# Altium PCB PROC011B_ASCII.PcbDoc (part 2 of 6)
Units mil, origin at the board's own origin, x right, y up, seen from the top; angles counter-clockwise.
Board outline 3304 x 2569 mil, 6 copper layers (TOP, L2-GND1, L3-GND/SIG, L4-GND/SIG, L5-GND2, BOTTOM), stack 55.77 mil thick; 376 components, 289 nets, 1284 pads, 1755 vias.
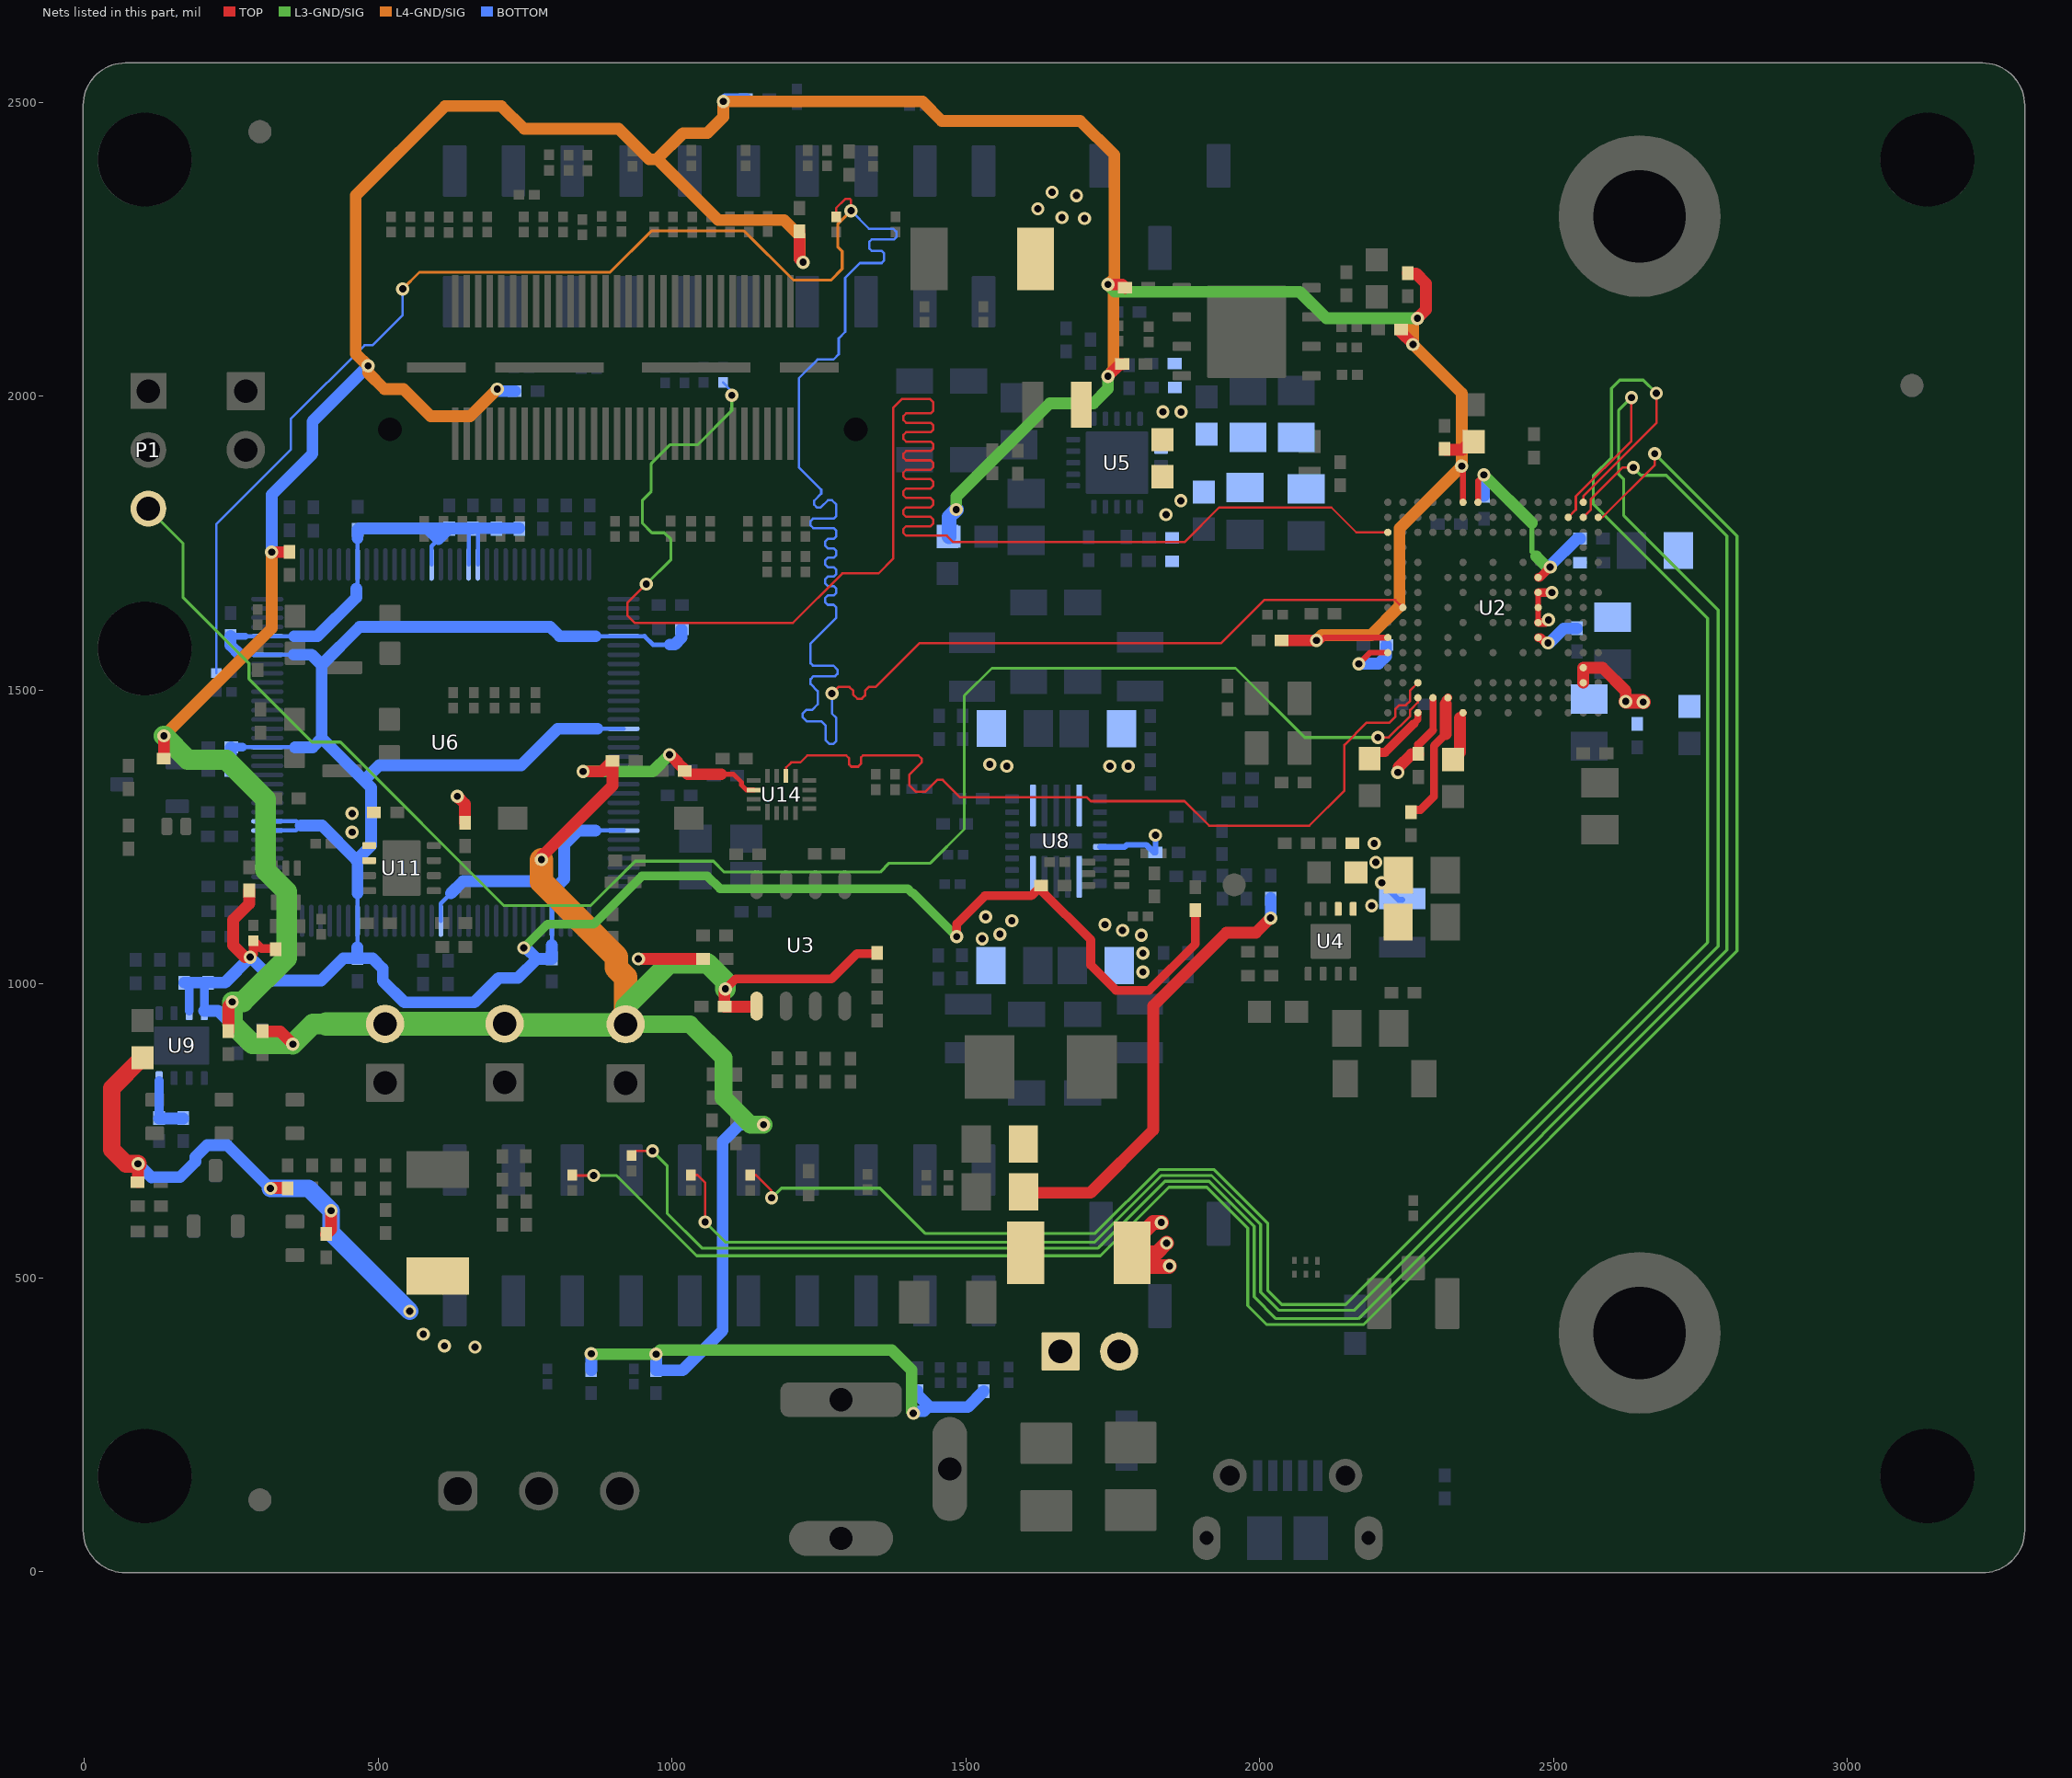
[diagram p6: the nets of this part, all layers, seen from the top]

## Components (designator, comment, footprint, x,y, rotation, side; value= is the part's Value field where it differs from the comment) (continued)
R204 "CRCW04023R83FKED" 0402L 1493.45,1029.3 r270 bottom
R205 "CRCW04023R83FKED" 0402L 1836.65,1032.8 r270 bottom
R206 "CRCW040210K0FKED" 0402L 918.61,1379.34 r180 top locked
R208 "CRCW040210K0FKED" 0402L 1105.82,1383.62 r180 top locked
R210 "CRCW02010000Z0ED" 0201 2026.48,1628.29 r0 top
R211 "CRCW02010000Z0ED" 0201 1421.16,1331.73 r0 bottom
S2 "CHS-01TB" SW_CHS-01TB 878.93,1281.85 r90 top locked
SW1 "KMR243GLFG" SW_KMR243GLFG 439.4,1594.12 r180 top
SW2 "KMR243GLFG" SW_KMR243GLFG 438.45,1418.5 r180 top
U1 "MX25V1635FZNQ" WSON-8L_6x5MM_EP 1977.88,2109.68 r0 top
U2 "X1642BIGABL" ABL0161B 2397.3,1640.4 r180 top
U3 "TCAN1042HGVDQ1" D0008A_L 1219.06,1065.48 r270 top
U4 "TPS7A8101QDRBRQ1" DRB0008A 2120.93,1072.47 r270 top
U5 "TPS7A8801RTJR" RTJ0020D 1757.37,1886.82 r0 bottom
U6 "TM4C1294NCPDTT3" PDT0128A 614.54,1410.54 r0 bottom
U7 "LM4040C25QDBZR" DBZ0003A_N 110.83,1339.59 r180 bottom
U8 "LP87524BRNFRQ1" RNF0026C 1653.75,1243 r0 bottom
U9 "TPS79601DRBR" DRB0008B 165.58,894.88 r270 bottom
U10 "TPD4E004DRYR" DRY0006A 2078.75,518 r270 top
U11 "TPS79601DRBR" DRB0008B 539.65,1197 r0 top
U12 "TMP112AIDRLR" DRL0006A 1736.25,1187.4 r0 top
U13 "TMP112AIDRLR" DRL0006A 342.75,1167.9 r270 top
U14 "TS3A5018RSVR" RSV0016A 1186.27,1322.21 r90 top locked
Y1 "CX3225SA40000D0PTWCC" KYOCERA_CX3225SA 2031.47,1443.64 r0 top
Y2 "NX3225SA-16.000M-STD-CRS-2" NDK_NX3225SA 1083.39,1215.58 r270 bottom
ZZ1 "This Assembly Note is for PCB labels only" AssemblyNoteLabel -70,3780 r0 top
ZZ2 "These assemblies are ESD sensitive, ESD precautions shall be observed." AssemblyNote -70,3690 r0 top
ZZ3 "These assemblies must be clean and free from flux and all contaminants. Use of no clean flux is not acceptable." AssemblyNote -70,3590 r0 top
ZZ4 "These assemblies must comply with workmanship standards IPC-A-610 Class 2, unless otherwise specified." AssemblyNote -70,3500 r0 top
ZZ5 "Micro USB cable, Brackets, Screws, Nuts, Jumpers and Bump on need to be place in a plastic bag" AssemblyNote -76,3400 r90 top

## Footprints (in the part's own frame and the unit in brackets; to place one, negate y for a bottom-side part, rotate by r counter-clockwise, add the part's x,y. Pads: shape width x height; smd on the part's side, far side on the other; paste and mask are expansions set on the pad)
0201 [mm] "Data from Kemet datasheet CC101_COM dated 7/28/11"
  rect 0.46x0.42 smd: 1(-0.33,0) 2(0.33,0)
0201_033 [mm] "SMD, 2-Leads, Height 0.33mm"
  rect 0.46x0.42 smd mask+0: 1(-0.33,0) 2(0.33,0)
0201_Silk [mm] "Data from Kemet datasheet CC101_COM dated 7/28/11"
  rect 0.46x0.42 smd mask+0: 1(-0.33,0) 2(0.33,0)
  silkscreen extent -0.75,-0.4 0.75,0.4
0402_065L [mm] "0402"
  rect 0.6x0.5 smd: 1(-0.5,0) 2(0.5,0)
0402L [mm] "0402 from SM-752 data"
  rect 0.6x0.5 smd: 1(-0.5,0) 2(0.5,0)
0603 [mm] "0603 from SM-752 data"
  rect 1x0.95 smd: 1(-0.8,0) 2(0.8,0)
  silkscreen extent -1.52,-0.69 1.52,0.69
0805_HV [mil] "0805 with 30mil clearance between pads"
  rect 50x63 smd: 1(-40,0) 2(40,0)
  silkscreen extent -74,-40 74,40
1206 [mm] "1206 from SM-752 data"
  rect 1.3x1.85 smd: 1(-1.45,0) 2(1.45,0)
  silkscreen extent -2.4,-1.21 2.4,1.21
1206_180 [mm] "1206_180"
  rect 1.1x1.6 smd: 1(-1.7,0) 2(1.7,0)
  silkscreen extent -0.9,-1 0.9,1
2010 [mm] "Chip Capacitor, Body 5.08x2.54mm, IPC Medium Density"
  rect 1.6x2.7 smd: 1(-2.3,0) 2(2.3,0)
  silkscreen extent -3.29,-1.65 3.42,1.65
3528-21 [mm] "Medium Density IPC, based on Kemet datasheet 2016-10-20"
  rrect6% 1.8x2.23 smd: 1(-1.46,0) 2(1.46,0)
  silkscreen extent -2.29,-1.5 0.76,1.5
ABL0161B [mm] "BGA, 161-Balls, Body 10.4x10.4mm, Pitch 0.65mm"
  round 0.32 smd: A1(-4.55,4.55) A2(-3.9,4.55) A3(-3.25,4.55) A5(-1.95,4.55) A7(-0.65,4.55) A9(0.65,4.55) A10(1.3,4.55) A13(3.25,4.55) A14(3.9,4.55) A15(4.55,4.55) B1(-4.55,3.9) B2(-3.9,3.9) B3(-3.25,3.9) B4(-2.6,3.9) B5(-1.95,3.9) B6(-1.3,3.9) B7(-0.65,3.9) B8(0,3.9) B9(0.65,3.9) B10(1.3,3.9) B11(1.95,3.9) B12(2.6,3.9) B13(3.25,3.9) B14(3.9,3.9) B15(4.55,3.9) C1(-4.55,3.25) C2(-3.9,3.25) C3(-3.25,3.25) C4(-2.6,3.25) C5(-1.95,3.25) C6(-1.3,3.25) C7(-0.65,3.25) C8(0,3.25) C9(0.65,3.25) C13(3.25,3.25) C14(3.9,3.25) C15(4.55,3.25) D2(-3.9,2.6) D13(3.25,2.6) D14(3.9,2.6) D15(4.55,2.6) E1(-4.55,1.95) E2(-3.9,1.95) E3(-3.25,1.95) E5(-1.95,1.95) E6(-1.3,1.95) E8(0,1.95) E10(1.3,1.95) E11(1.95,1.95) E13(3.25,1.95) E14(3.9,1.95) E15(4.55,1.95) F2(-3.9,1.3) F3(-3.25,1.3) F5(-1.95,1.3) F9(0.65,1.3) F11(1.95,1.3) F13(3.25,1.3) F14(3.9,1.3) F15(4.55,1.3) G1(-4.55,0.65) G2(-3.9,0.65) G3(-3.25,0.65) G5(-1.95,0.65) G6(-1.3,0.65) G7(-0.65,0.65) G8(0,0.65) G10(1.3,0.65) G13(3.25,0.65) G14(3.9,0.65) G15(4.55,0.65) H2(-3.9,0) H3(-3.25,0) H5(-1.95,0) H7(-0.65,0) H9(0.65,0) H11(1.95,0) H13(3.25,0) H14(3.9,0) H15(4.55,0) J1(-4.55,-0.65) J2(-3.9,-0.65) J3(-3.25,-0.65) J5(-1.95,-0.65) J6(-1.3,-0.65) J7(-0.65,-0.65) J8(0,-0.65) J10(1.3,-0.65) J13(3.25,-0.65) J14(3.9,-0.65) J15(4.55,-0.65) K2(-3.9,-1.3) K3(-3.25,-1.3) K5(-1.95,-1.3) K7(-0.65,-1.3) K8(0,-1.3) K9(0.65,-1.3) K10(1.3,-1.3) K11(1.95,-1.3) K13(3.25,-1.3) K14(3.9,-1.3) K15(4.55,-1.3) L1(-4.55,-1.95) L2(-3.9,-1.95) L3(-3.25,-1.95) L5(-1.95,-1.95) L6(-1.3,-1.95) L8(0,-1.95) L10(1.3,-1.95) L13(3.25,-1.95) L14(3.9,-1.95) L15(4.55,-1.95) M2(-3.9,-2.6) M3(-3.25,-2.6) M14(3.9,-2.6) M15(4.55,-2.6) N1(-4.55,-3.25) N2(-3.9,-3.25) N3(-3.25,-3.25) N4(-2.6,-3.25) N5(-1.95,-3.25) N6(-1.3,-3.25) N7(-0.65,-3.25) N8(0,-3.25) N9(0.65,-3.25) N10(1.3,-3.25) N11(1.95,-3.25) N12(2.6,-3.25) N13(3.25,-3.25) N14(3.9,-3.25) N15(4.55,-3.25) P1(-4.55,-3.9) P2(-3.9,-3.9) P3(-3.25,-3.9) P4(-2.6,-3.9) P5(-1.95,-3.9) P6(-1.3,-3.9) P7(-0.65,-3.9) P8(0,-3.9) P9(0.65,-3.9) P10(1.3,-3.9) P11(1.95,-3.9) P12(2.6,-3.9) P13(3.25,-3.9) P14(3.9,-3.9) P15(4.55,-3.9) R1(-4.55,-4.55) R2(-3.9,-4.55) R3(-3.25,-4.55) R4(-2.6,-4.55) R5(-1.95,-4.55) R6(-1.3,-4.55) R7(-0.65,-4.55) R8(0,-4.55) R9(0.65,-4.55) R10(1.3,-4.55) R11(1.95,-4.55) R12(2.6,-4.55) R13(3.25,-4.55) R14(3.9,-4.55) R15(4.55,-4.55)
  silkscreen extent -5.3,-5.3 5.3,5.3
AssemblyNote [mil] "Assembly Note"
AssemblyNoteLabel [mil] "Assembly Note for PCB Labels"
CE_Mark_5mm [mil] "Minimum text height for CE Mark"
CONN_105017-0001 [mm] "Molex Micro USB-B"
  rect 0.4x1.35 smd: 1(-1.3,1.35) 2(-0.65,1.35) 3(0,1.35) 4(0.65,1.35) 5(1.3,1.35)
  oval 1.2x1.9 hole 0.6 slot 1.3 at 90 deg: 6(-3.5,-1.35) 9(3.5,-1.35)
  rect 1.5x1.9 smd: 7(-1,-1.35) 8(1,-1.35)
  round 1.45 hole 0.85: 10(2.5,1.35) 11(-2.5,1.35)
  TOP region: 3.5,-2.3 2.3,-2.3 2.3,-0.4 3.5,-0.4
  TOP region: -3.5,-0.4 -2.3,-0.4 -2.3,-2.3 -3.5,-2.3
  silkscreen extent -4.1,-0.2 4.1,1.4
CUI_PJ-002AH [mm] "DC POWER JACK, R/A, TH"
  rrect50% 1.5x5.25 hole 1 square: 1(-3,0)
  oval 1.5x4.5 hole 1 square: 2(3,0)
  oval 4.5x1.5 hole 1 square: 3(0,4.7)
  silkscreen extent -4.1,-4.5 10.7,4.5
D0008A_L [mm] "SOIC, 8-Leads, Body 4.9x3.9mm, Pitch 1.27mm, IPC High Density"
  oval 1.25x0.55 smd: 1(-2.625,1.905) 2(-2.625,0.635) 3(-2.625,-0.635) 4(-2.625,-1.905) 5(2.625,-1.905) 6(2.625,-0.635) 7(2.625,0.635) 8(2.625,1.905)
  silkscreen extent -3.1,-2.5 0.9,2.5
DBZ0003A_N [mm] "SOT23, 3-Leads, Body 2.9x1.3mm, Pitch 0.95mm, Lead Span 2.4mm, IPC Medium Density"
  rrect17% 1x0.6 smd: 1(-1.2,0.95) 2(-1.2,-0.95) 3(1.2,0)
  silkscreen extent 0.2,-1.5 0.7,1.5
DFE252012P [mm] "TOKO, Pad sizes increased as per request"
  rect 0.9x2 smd: 1(-1.05,0) 2(1.05,0)
  silkscreen extent -0.3,-1.2 0.3,1.2
DRB0008A [mm] "SON, 8-Leads, Body 3x3mm, Pitch 0.65mm, Thermal Pad 1.75x1.5mm, TI Recommended"
  rrect33% 0.6x0.3 smd: 1(-1.4,0.975) 2(-1.4,0.325) 3(-1.4,-0.325) 4(-1.4,-0.975) 5(1.4,-0.975) 6(1.4,-0.325) 7(1.4,0.325) 8(1.4,0.975)
  rrect7% 1.5x1.75 smd paste-0.75: 9(0,0)
  silkscreen extent -1.73,-1.73 1.73,1.73
DRB0008B [mm] "SON, 8-Leads, Body 3x3mm, Pitch 0.65mm, Thermal Pad 2.4x1.65mm, TI Recommended"
  rrect33% 0.6x0.3 smd: 1(-1.4,0.975) 2(-1.4,0.325) 3(-1.4,-0.325) 4(-1.4,-0.975) 5(1.4,-0.975) 6(1.4,-0.325) 7(1.4,0.325) 8(1.4,0.975)
  rrect6% 1.65x2.4 smd paste-1.2: 9(0,0)
  silkscreen extent -1.73,-1.73 1.73,1.73
DRL0006A [mm] "SOTFL, 6-Flat Leads, Body 1.2x1.6x0.6mm, Pitch 0.5mm, TI recommended"
  rrect33% 0.67x0.3 smd: 1(-0.74,0.5) 2(-0.74,0) 3(-0.74,-0.5) 4(0.74,-0.5) 5(0.74,0) 6(0.74,0.5)
  silkscreen extent -0.9,-0.95 0.5,0.95
DRY0006A [mm] "PSON, 6-Leads, Body 1x1.45mm, Pitch 0.5mm, TI Recommended"
  rect 0.35x0.2 smd: 1(-0.275,0.5)
  rect 0.3x0.2 smd: 2(-0.3,0) 3(-0.3,-0.5) 4(0.3,-0.5) 5(0.3,0) 6(0.3,0.5)
  silkscreen extent -0.5,-0.85 0.2,0.85
ESD_Overlay_Small [mil]
  silkscreen extent -62,-48 64,61
FCC_disclaimer [mil]
FIDUCIAL10-20 [mm]
  round 1 smd mask+0: 1(0,0)
  TOP keep-out circle w1.178: c0,0 r0.5
Fiducial10-20 [mm]
  round 1 smd mask+0: 1(0,0)
  TOP keep-out circle w1.178: c0,0 r0.5
IEC_HotSurface_Small [mil]
  silkscreen extent -107,-93 107,92
JOHNSON_128-0711-201 [mm] "UMC Straight Jack Receptacle, 50 Ohm, SMT"
  rrect10% 1x1.05 smd: 1(0,1.525)
  rrect10% 1.05x2.2 smd: 2(-1.475,0) 3(1.475,0)
  silkscreen extent -0.6,-1.3 0.6,-1.3
KYOCERA_CX3225SA [mm] "SMD, 4-Leads, Body 3.2x2.5mm"
  rrect10% 1.05x1.45 smd: 1(-0.925,1.075) 2(-0.925,-1.075) 3(0.925,-1.075) 4(0.925,1.075)
  silkscreen extent -1.83,1.05 -1.71,1.18
Label_650x200 [mil] "Thermal Transfer Label"
  round 1 on Mech13: 0(0,0)
  silkscreen extent -325,-100 325,100
NDK_NX3225SA [mm] "NDK"
  rect 1.2x1.4 smd: 1(-0.8,1.1) 2(-0.8,-1.1) 3(0.8,-1.1) 4(0.8,1.1)
ON-SHORE_OSTTE030161 [mm] "Terminal Block, 3.5mm, 3x1, TH"
  rrect50% 1.7x1.7 hole 1.2: 1(-3.5,0)
  round 1.7 hole 1.2: 2(0,0) 3(3.5,0)
  silkscreen extent -5.25,-3.6 5.25,4.05
PDT0128A [mm] "Thin QFP, 128-Leads, Body 14x14mm, Pitch 0.4mm"
  oval 1.4x0.2 smd: 1(-7.7,6.2) 2(-7.7,5.8) 3(-7.7,5.4) 4(-7.7,5) 5(-7.7,4.6) 6(-7.7,4.2) 7(-7.7,3.8) 8(-7.7,3.4) 9(-7.7,3) 10(-7.7,2.6) 11(-7.7,2.2) 12(-7.7,1.8) 13(-7.7,1.4) 14(-7.7,1) 15(-7.7,0.6) 16(-7.7,0.2) 17(-7.7,-0.2) 18(-7.7,-0.6) 19(-7.7,-1) 20(-7.7,-1.4) 21(-7.7,-1.8) 22(-7.7,-2.2) 23(-7.7,-2.6) 24(-7.7,-3) 25(-7.7,-3.4) 26(-7.7,-3.8) 27(-7.7,-4.2) 28(-7.7,-4.6) 29(-7.7,-5) 30(-7.7,-5.4) 31(-7.7,-5.8) 32(-7.7,-6.2) 65(7.7,-6.2) 66(7.7,-5.8) 67(7.7,-5.4) 68(7.7,-5) 69(7.7,-4.6) 70(7.7,-4.2) 71(7.7,-3.8) 72(7.7,-3.4) 73(7.7,-3) 74(7.7,-2.6) 75(7.7,-2.2) 76(7.7,-1.8) 77(7.7,-1.4) 78(7.7,-1) 79(7.7,-0.6) 80(7.7,-0.2) 81(7.7,0.2) 82(7.7,0.6) 83(7.7,1) 84(7.7,1.4) 85(7.7,1.8) 86(7.7,2.2) 87(7.7,2.6) 88(7.7,3) 89(7.7,3.4) 90(7.7,3.8) 91(7.7,4.2) 92(7.7,4.6) 93(7.7,5) 94(7.7,5.4) 95(7.7,5.8) 96(7.7,6.2)
  oval 0.2x1.4 smd: 33(-6.2,-7.7) 34(-5.8,-7.7) 35(-5.4,-7.7) 36(-5,-7.7) 37(-4.6,-7.7) 38(-4.2,-7.7) 39(-3.8,-7.7) 40(-3.4,-7.7) 41(-3,-7.7) 42(-2.6,-7.7) 43(-2.2,-7.7) 44(-1.8,-7.7) 45(-1.4,-7.7) 46(-1,-7.7) 47(-0.6,-7.7) 48(-0.2,-7.7) 49(0.2,-7.7) 50(0.6,-7.7) 51(1,-7.7) 52(1.4,-7.7) 53(1.8,-7.7) 54(2.2,-7.7) 55(2.6,-7.7) 56(3,-7.7) 57(3.4,-7.7) 58(3.8,-7.7) 59(4.2,-7.7) 60(4.6,-7.7) 61(5,-7.7) 62(5.4,-7.7) 63(5.8,-7.7) 64(6.2,-7.7) 97(6.2,7.7) 98(5.8,7.7) 99(5.4,7.7) 100(5,7.7) 101(4.6,7.7) 102(4.2,7.7) 103(3.8,7.7) 104(3.4,7.7) 105(3,7.7) 106(2.6,7.7) 107(2.2,7.7) 108(1.8,7.7) 109(1.4,7.7) 110(1,7.7) 111(0.6,7.7) 112(0.2,7.7) 113(-0.2,7.7) 114(-0.6,7.7) 115(-1,7.7) 116(-1.4,7.7) 117(-1.8,7.7) 118(-2.2,7.7) 119(-2.6,7.7) 120(-3,7.7) 121(-3.4,7.7) 122(-3.8,7.7) 123(-4.2,7.7) 124(-4.6,7.7) 125(-5,7.7) 126(-5.4,7.7) 127(-5.8,7.7) 128(-6.2,7.7)
  silkscreen extent -7.7,-6.3 6.3,6.99
RNF0026C [mm] "QFN, 26-Leads, Body 4x4.5mm, Pitch 0.5mm"
  rrect25% 0.6x0.4 smd paste-0.3: 1(-1.9,1.825) 8(-1.9,-1.825) 14(1.9,-1.825) 21(1.9,1.825)
  rrect40% 0.6x0.25 smd paste+0: 2(-1.9,1.25) 3(-1.9,0.75) 4(-1.9,0.25) 5(-1.9,-0.25) 6(-1.9,-0.75) 7(-1.9,-1.25) 15(1.9,-1.25) 16(1.9,-0.75) 17(1.9,-0.25) 18(1.9,0.25) 19(1.9,0.75) 20(1.9,1.25)
  rrect40% 0.25x1.82 smd paste-1: 9(-1,-1.54) 10(-0.5,-1.54) 11(0,-1.54) 12(0.5,-1.54) 13(1,-1.54) 22(1,1.54) 23(0.5,1.54) 24(0,1.54) 25(-0.5,1.54) 26(-1,1.54)
  rrect15% 2.24x0.66 smd paste-1: 27(0,0)
  rrect50% 0.6x0.3 on Bottom Paste: ""(-1.9,-1.775) ""(-1.9,1.775) ""(1.9,-1.775) ""(1.9,1.775)
  rrect50% 0.3x0.825 on Bottom Paste: ""(-1.575,-2.037) ""(-1.575,2.037) ""(1.575,-2.037) ""(1.575,2.037)
  rrect50% 0.25x0.81 on Bottom Paste: ""(-1,-2.045) ""(-1,-1.035) ""(-1,1.035) ""(-1,2.045) ""(-0.5,-2.045) ""(-0.5,-1.035) ""(-0.5,1.035) ""(-0.5,2.045) ""(0,-2.045) ""(0,-1.035) ""(0,1.035) ""(0,2.045) ""(0.5,-2.045) ""(0.5,-1.035) ""(0.5,1.035) ""(0.5,2.045) ""(1,-2.045) ""(1,-1.035) ""(1,1.035) ""(1,2.045)
  rrect50% 0.98x0.66 on Bottom Paste: ""(-0.59,0) ""(0.59,0)
  silkscreen extent -2.45,-2.7 2.45,2.7
RSV0016A [mm] "QFN, 16-Leads, Body 1.8x2.6mm, Pitch 0.4mm, TI Recommended"
  rect 0.7x0.2 smd: 1(-0.75,0.6)
  rect 0.6x0.2 smd: 2(-0.8,0.2) 3(-0.8,-0.2) 4(-0.8,-0.6) 9(0.8,-0.6) 10(0.8,-0.2) 11(0.8,0.2) 12(0.8,0.6)
  rect 0.2x0.6 smd: 5(-0.6,-1.2) 6(-0.2,-1.2) 7(0.2,-1.2) 8(0.6,-1.2) 13(0.6,1.2) 14(0.2,1.2) 15(-0.2,1.2) 16(-0.6,1.2)
  silkscreen extent -1.08,-1.33 1.08,1.45
RTJ0020D [mm] "QFN, 20-Leads, Body 4x4mm, Pitch 0.5mm, Thermal Pad 2.7x2.7mm, TI Recommended"
  rrect42% 0.6x0.24 smd: 1(-1.9,1) 2(-1.9,0.5) 3(-1.9,0) 4(-1.9,-0.5) 5(-1.9,-1) 11(1.9,-1) 12(1.9,-0.5) 13(1.9,0) 14(1.9,0.5) 15(1.9,1)
  rrect42% 0.24x0.6 smd: 6(-1,-1.9) 7(-0.5,-1.9) 8(0,-1.9) 9(0.5,-1.9) 10(1,-1.9) 16(1,1.9) 17(0.5,1.9) 18(0,1.9) 19(-0.5,1.9) 20(-1,1.9)
  rrect50% 1.19x1.19 on Bottom Paste: 21(-0.695,-0.695) 21(-0.695,0.695) 21(0.695,-0.695) 21(0.695,0.695)
  rrect4% 2.7x2.7 smd paste-1.4: 21(0,0)
  silkscreen extent -2.22,-2.22 2.23,2.22
SAMTEC_QSH-030-01-X-D-A [mm] "Receptacle, 0.5 mm, 30x2, TH"
  rect 2.27x0.279 smd: 1(-2.865,7.25) 2(2.865,7.25) 3(-2.865,6.75) 4(2.865,6.75) 5(-2.865,6.25) 6(2.865,6.25) 7(-2.865,5.75) 8(2.865,5.75) 9(-2.865,5.25) 10(2.865,5.25) 11(-2.865,4.75) 12(2.865,4.75) 13(-2.865,4.25) 14(2.865,4.25) 15(-2.865,3.75) 16(2.865,3.75) 17(-2.865,3.25) 18(2.865,3.25) 19(-2.865,2.75) 20(2.865,2.75) 21(-2.865,2.25) 22(2.865,2.25) 23(-2.865,1.75) 24(2.865,1.75) 25(-2.865,1.25) 26(2.865,1.25) 27(-2.865,0.75) 28(2.865,0.75) 29(-2.865,0.25) 30(2.865,0.25) 31(-2.865,-0.25) 32(2.865,-0.25) 33(-2.865,-0.75) 34(2.865,-0.75) 35(-2.865,-1.25) 36(2.865,-1.25) 37(-2.865,-1.75) 38(2.865,-1.75) 39(-2.865,-2.25) 40(2.865,-2.25) 41(-2.865,-2.75) 42(2.865,-2.75) 43(-2.865,-3.25) 44(2.865,-3.25) 45(-2.865,-3.75) 46(2.865,-3.75) 47(-2.865,-4.25) 48(2.865,-4.25) 49(-2.865,-4.75) 50(2.865,-4.75) 51(-2.865,-5.25) 52(2.865,-5.25) 53(-2.865,-5.75) 54(2.865,-5.75) 55(-2.865,-6.25) 56(2.865,-6.25) 57(-2.865,-6.75) 58(2.865,-6.75) 59(-2.865,-7.25) 60(2.865,-7.25)
  round 0 hole 1.02 unplated mask+0: MH1(2.67,10.065) MH2(2.67,-10.065)
  rect 0.43x2.54 smd: MP1(0,8.065) MP4(0,-8.065)
  rect 0.43x4.7 smd: MP2(0,3.175) MP3(0,-3.175)
  silkscreen extent -3.9,-10.66 3.62,10.66
SAMTEC_SSM-103-X-SV [mm] "Receptacle, 2.54mm, 3x1, SMT"
  rrect10% 1.02x1.905 smd: 1(-2.54,-1.777) 2(0,1.777) 3(2.54,-1.777)
  silkscreen extent -3.81,-2.27 3.81,1.28
SAMTEC_SSM-110-X-DV [mm] "Receptacle, 2.54mm, 10x2, SMT"
  rrect10% 1.02x2.22 smd: 1(-11.43,2.825) 2(-11.43,-2.825) 3(-8.89,2.825) 4(-8.89,-2.825) 5(-6.35,2.825) 6(-6.35,-2.825) 7(-3.81,2.825) 8(-3.81,-2.825) 9(-1.27,2.825) 10(-1.27,-2.825) 11(1.27,2.825) 12(1.27,-2.825) 13(3.81,2.825) 14(3.81,-2.825) 15(6.35,2.825) 16(6.35,-2.825) 17(8.89,2.825) 18(8.89,-2.825) 19(11.43,2.825) 20(11.43,-2.825)
  silkscreen extent -13.02,-2.54 12.7,2.54
SAMTEC_TSW-103-07-T-S [mm] "Header, 2.54 mm, 3x1, TH"
  rect 1.55x1.55 hole 1.02: 1(-2.54,0)
  round 1.55 hole 1.02: 2(0,0) 3(2.54,0)
  silkscreen extent -3.81,-1.75 3.81,1.27
SMB [mil] "Molded Diode, 2-Leads, Body 5.4x3.6mm, IPC Medium Density, based on OnSemi component dimensions"
  rect 85x107.99 smd: 1(-87.01,0) 2(87.01,0)
  silkscreen extent -155,-82 125,82
SOD-882 [mm] "Skyworks"
  rrect42% 0.475x0.75 smd: 1(-0.412,0) 2(0.412,0)
  silkscreen extent -1.1,-0.35 -0.87,0.35
SOT-23 [mm] "SOT23, 3-Leads, Body 2.9x1.3mm, Pitch 0.95mm, Lead Span 2.5mm, IPC Medium Density"
  rrect50% 1x0.6 smd: 1(-1.2,0.95) 2(-1.2,-0.95) 3(1.2,0)
  silkscreen extent -1.62,-1.5 0.7,1.5
SW_CHS-01TB [mm] "CHS Recommended footprint"
  rect 1x1.27 smd: 1(0,3.81) 2(0,-3.81)
  silkscreen extent -1.3,-4.05 1.3,4.05
SW_KMR243GLFG [mm] "SMD, 5-Leads, Body 4.2x2.8mm"
  rrect11% 0.9x1 smd: 1(-2.05,0.8) 2(2.05,0.8) 3(-2.05,-0.8) 4(2.05,-0.8)
  rrect18% 1.7x0.55 smd: 5(0,1.425)
  silkscreen extent -3.1,0.7 -2.9,0.9
TI_Stacked_Overlay_Small [mil]
TLMX1000_RED [mm] "SMD, 2-Leads, Body 1.6x0.8mm"
  rrect17% 0.6x0.8 smd: 1(-0.725,0) 2(0.725,0)
  silkscreen extent -0.97,-0.8 1.6,0.8
TLMX1000_YELLOW [mm] "SMD, 2-Leads, Body 1.6x0.8mm"
  rrect17% 0.6x0.8 smd: 1(-0.725,0) 2(0.725,0)
  silkscreen extent -0.97,-0.8 1.6,0.8
TSW-102-07-X-S [mm] "Samtec 100 mil 1x2 head, 230 mil above insulator"
  rrect6% 1.65x1.65 hole 1.016: 1(-1.27,0)
  round 1.65 hole 1.016: 2(1.27,0)
  silkscreen extent -3.42,-1.4 2.72,1.4
WEEE_Minimum [mil] "WEEElie bin"
  silkscreen extent 22,-71 54,74
WSON-8L_6x5MM_EP [mm] "SMD, 8-Leads, Body 6x5mm, Pitch 1.27mm"
  rrect25% 0.8x0.4 smd: 1(-2.8,1.905) 2(-2.8,0.635) 3(-2.8,-0.635) 4(-2.8,-1.905) 5(2.8,-1.905) 6(2.8,-0.635) 7(2.8,0.635) 8(2.8,1.905)
  rrect3% 3.4x4 smd paste-3: 9(0,0)
  rrect7% 1.468x1.698 on Top Paste: ""(-0.834,-0.949) ""(-0.834,0.949) ""(0.834,-0.949) ""(0.834,0.949)
  silkscreen extent -3.2,-2.7 3.2,2.7

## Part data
C1 C13 C14 C33 C36: library part CMP-0007136-5, "CAP, CERM, 1 uF, 16 V, +/- 10%, X7R, AEC-Q200 Grade 1, 0603"
C2 C21: library part CMP-0006325-2, "CAP, CERM, 0.1 uF, 50 V, +/- 10%, X7R, AEC-Q200 Grade 1, 0402"
C3 C5 C7 C10 C12 C39 C47 C48 C51 C53 C56 C57 C68 C84 C90: library part CMP-0078265-1, "CAP, CERM, 0.22 µF, 16 V,+/- 10%, X7R, AEC-Q200 Grade 1, 0402"
C4 C6 C11: library part CMP-0006351-2, "CAP, CERM, 0.1 uF, 16 V, +/- 10%, X7R, 0402"
C8: library part CMP-0078219-1, "CAP, CERM, 0.1 µF, 10 V,+/- 10%, X7S, 0201"
C9 C15: library part CMP-0006367-2, "CAP, CERM, 4.7 pF, 50 V, +/- 2%, C0G/NP0, 0402"
C16 C20 C42 C43 C49 C64 C67 C71 C75 C76 C79 C91 C92 C97: library part CMP-0078241-1, "CAP, CERM, 0.1 µF, 10 V,+/- 10%, X7R, 0402"
C17 C19 C23 C32 C34 C35 C37 C38 C40 C45 C52 C58 C59 C60 C65 C72 C73 C83: library part CMP-0008017-2, "CAP, CERM, 10 uF, 10 V, +/- 10%, X7R, 0805"
C18 C22: library part CMP-0007138-4, "CAP, CERM, 0.47 uF, 16 V, +/- 10%, X7R, AEC-Q200 Grade 1, 0603"
C24: library part CMP-0078221-1, "CAP, CERM, 4700 pF, 50 V,+/- 10%, X7R, 0402"
C25 C30 C31: library part CMP-0008770-2, "CAP, CERM, 22 uF, 6.3 V, +/- 10%, X7R, AEC-Q200 Grade 1, 1206"
C26 C27: library part CMP-0078216-1, "CAP, TA, 47 µF, 10 V, +/- 10%, SMD"
C28 C29 C44 C46: library part CMP-0078224-1, "CAP, CERM, 0.01 µF, 50 V,+/- 10%, X8R, AEC-Q200 Grade 0, 0402"
C41 C61 C62 C85: library part CMP-0078222-1, "CAP, CERM, 1 µF, 6.3 V,+/- 20%, X7S, 0402"
C50: library part CMP-0078220-1, "CAP, CERM, 0.01 µF, 25 V,+/- 10%, X7R, 0402"
C54 C55 C81 C82: library part CMP-0008811-2, "CAP, CERM, 22 uF, 10 V, +/- 10%, X7R, AEC-Q200 Grade 1, 1206"
C63 C70: library part CMP-0006494-2, "CAP, CERM, 8 pF, 50 V, +/- 6%, C0G/NP0, 0402"
C66 C69: library part CMP-0078218-1, "CAP, CERM, 0.01 µF, 16 V,+/- 10%, X7R, 0402"
C74 C77 C80 C86: library part CMP-0006302-2, "CAP, CERM, 2.2 uF, 10 V, +/- 10%, X7S, 0402"
C78: library part CMP-0078217-1, "CAP, CERM, 15 pF, 50 V,+/- 1%, C0G/NP0, 0402"
C87 C89: library part CMP-0007134-5, "CAP, CERM, 2.2 uF, 6.3 V, +/- 10%, X7R, AEC-Q200 Grade 1, 0603"
C88: library part CMP-0006242-2, "CAP, CERM, 33 pF, 50 V, +/- 5%, C0G/NP0, 0402"
C93 C94 C95 C96: library part CMP-0078223-1, "CAP, CERM, 390 pF, 50 V,+/- 5%, C0G/NP0, AEC-Q200 Grade 0, 0402"
"CAUTION HOT SURFACE": library part CMP-0074837-1, "IEC 61010-1 Hot Surface Warning"
D2: library part CMP-0078187-1, "Diode, Schottky,  V, 0.01 A, SOD-882"
D3: library part CMP-0078243-1, "Diode, TVS, Uni, 5.8 V, 10.5 Vc, AEC-Q101, SMB"
DS1 DS2: library part CMP-0078197-1, "LED, Red, SMD"
DS3 DS4: library part CMP-0078196-1, "LED, Yellow, SMD"
"ESD Susceptible": library part CMP-0074840-1, "ESD Susceptible Symbol"
F1: library part CMP-0003458-1, "Fuse, 5 A, 32VAC/VDC, SMD"
FB1 FB2: library part CMP-0003364-1, "Ferrite Bead, 30 ohm @ 100 MHz, 4 A, 0805"
FID1 FID2 FID3 FID4 FID5 FID6 FID7: library part CMP-0077181-1, "Fiducial mark.  There is nothing to buy or mount."
J1: library part CMP-0075524-1, "Receptacle, 0.5 mm, 30x2, Gold, TH"
J2: library part CMP-0055788-1, "UMC Straight Jack Receptacle, 50 Ohm, Gold, SMT"
J3: library part CMP-0075352-1, "Terminal Block, 3.5mm, 3x1, Tin, R/A, TH"
J4 J7: library part CMP-0078183-1, "Receptacle, 2.54mm, 3x1, Gold with Tin tail, SMT"
J5 J6: library part CMP-0078182-1, "Receptacle, 2.54mm, 10x2, Gold with Tin tail, SMT"
J8: library part CMP-0055293-1, "Connector, Receptacle, Micro-USB Type B, R/A, Bottom Mount SMT"
L1 L2 L3 L4 L5 L6: library part CMP-0058946-1, "Inductor, Shielded, 470 nH, 4.7 A, 0.021 ohm, SMD"
LBL1: library part THT-14-423-10, "Thermal Transfer Printable Labels, 0.650\" W x 0.200\" H - 10,000 per roll"
Logo1: library part CMP-0074838-1, "Texas Instrument Corporate Signature"
Logo2: library part CMP-0074769-1
Logo3: library part CMP-0074847-1, "FCC_disclaimer"
P1: library part CMP-0075530-1, "Header, 2.54 mm, 3x1, Tin, TH"
P2 P3 P4 P5 P7: library part CMP-0075405-1, "Header, 100mil, 2x1, Gold, TH"
P6: library part CMP-0078270-1, "DC POWER JACK, R/A, TH"
Q1 Q2: library part CMP-0000947-2, "MOSFET, N-CH, 100 V, 0.17 A, SOT-23"
R1 R2 R4 R5 R6 R7 R8 R9 R10 R17 R18 R19 R20 R21 R22 R23 R24 R25 R26 R27 R28 R29 R30 R31 R32 R33 R35 R36 R48 R49 R50 R51 R52 R53 R58 R59 R60 R62 R63 R64 R65 R66 R67 R69 R70 R71 R72 R75 R76 R94 R102 R104 R105 R106 R108 R109 R111 R135 R136 R144 R146 R162 R163 R164 R165 R166 R167 R168 R169 R198 R199 R201: library part CMP-0027008-3, "RES, 0, 5%, 0.05 W, 0201"
R3 R13 R15 R16 R41 R43 R46 R47 R73 R74 R81 R83 R84 R86 R89 R91 R98 R113 R145 R148 R155 R170 R171 R177 R194 R197 R206 R208: library part CMP-0025958-2, "RES, 10.0 k, 1%, 0.063 W, 0402"
R11 R12 R37 R78 R97 R107 R119 R120 R128 R129 R141 R152 R159 R178 R196 R200: library part CMP-0026992-2, "RES, 0, 5%, 0.063 W, 0402"
R14 R110 R138 R158 R172 R173: library part CMP-0025950-2, "RES, 100 k, 1%, 0.063 W, 0402"
R34 R115 R118: library part CMP-0016044-2, "RES, 0, 5%, 0.75 W, AEC-Q200 Grade 0, 2010"
R38: library part CMP-0026395-1, "RES, 47.5 k, 1%, 0.063 W, 0402"
R39 R40 R42 R44 R45: library part CMP-0027275-2, "RES, 33.2, 1%, 0.05 W, 0201"
R54 R55 R56 R57 R179 R180 R181 R182 R183 R184 R185 R186 R187 R188 R189 R190 R191 R192: library part CMP-0078192-1, "RES, 20.0, 1%, 0.05 W, 0201"
R61: library part CMP-0026015-2, "RES, 14.0 k, 1%, 0.063 W, 0402"
R68 R77 R79 R80 R154: library part CMP-0026993-2, "RES, 100, 5%, 0.1 W, AEC-Q200 Grade 0, 0402"
R82: library part CMP-0025993-2, "RES, 12.7 k, 1%, 0.063 W, 0402"
R85 R87: library part CMP-0026491-1, "RES, 61.9, 1%, 0.063 W, 0402"
R88 R96 R114: library part CMP-0026574-1, "RES, 82.5 k, 1%, 0.063 W, AEC-Q200 Grade 0, 0402"
R90: library part CMP-0078194-1, "RES, 360, 5%, 0.1 W, AEC-Q200 Grade 0, 0402"
R92 R95 R99: library part CMP-0026557-1, "RES, 7.87 k, 1%, 0.063 W, AEC-Q200 Grade 0, 0402"
R93 R101 R112: library part CMP-0026542-1, "RES, 750, 1%, 0.063 W, AEC-Q200 Grade 0, 0402"
R100 R103 R116 R117 R160: library part CMP-0078212-1, "RES, 510, 5%, 0.1 W, AEC-Q200 Grade 0, 0402"
R121 R132: library part CMP-0078211-1, "RES, 3.00 k, 1%, 0.063 W, AEC-Q200 Grade 0, 0402"
R122 R131 R139: library part CMP-0026099-1, "RES, 1.96 k, 1%, 0.063 W, 0402"
R123 R124 R126 R127 R140: library part CMP-0026071-2, "RES, 1.00 k, 1%, 0.063 W, 0402"
R125: library part CMP-0026413-1, "RES, 4.87 k, 1%, 0.063 W, 0402"
R130 R133 R137 R161 R175 R176 R195: library part CMP-0025884-3, "RES, 0, 5%, 0.125 W, 0603"
R134: library part CMP-0026404-1, "RES, 49.9, 1%, 0.063 W, 0402"
R142 R150: library part CMP-0026701-1, "RES, 4.99 k, 1%, 0.1 W, AEC-Q200 Grade 0, 0402"
R143 R147: library part CMP-0026414-1, "RES, 4.99 k, 1%, 0.063 W, 0402"
R149: library part CMP-0078193-1, "RES, 1.0 k, 5%, 0.1 W, AEC-Q200 Grade 0, 0402"
R151 R153: library part CMP-0078210-1, "RES, 330 k, 1%, 0.063 W, AEC-Q200 Grade 0, 0402"
R156: library part CMP-0026403-1, "RES, 49.9 k, 1%, 0.063 W, 0402"
R157 R174: library part CMP-0078244-1, "RES, 30.0 k, 1%, 0.063 W, AEC-Q200 Grade 0, 0402"
R193: library part CMP-0078213-1, "RES, 35000, 0.1%, 0.05 W, 0402"
R202 R203 R204 R205: library part CMP-0026363-1, "RES, 3.83, 1%, 0.063 W, 0402"
R210 R211: library part CMP-0027008-4, "RES, 0, 5%, 0.05 W, 0201"
S2: library part CMP-0002163-2, "Switch, Slide, SPST, Top Slide, SMT"
SW1 SW2: library part CMP-0002325-1, "Switch, SPST-NO, Off-Mom, 0.01 A, 32 VDC, SMD"
U1: library part CMP-0079267-1, "2.3V-3.6V, 16M-BIT [x 1/x 2/x 4] CMOS FLASH Memory, WSON-8"
U2: library part CMP-0077311-2, "Single-Chip 77- and 79-GHz FMCW Radar Sensor, ABL0161B (FCBGA-161)"
U3: library part CMP-0075992-1, "Automotive Fault Protected CAN Transceiver With Flexible Data-Rate, D0008A (SOIC-8)"
U4: library part CMP-0073870-2, "Automotive Low-Noise, Wide-Bandwidth, High PSRR, Low-Dropout 1-A Linear Regulator, DRB0008A (VSON-8)"
U5: library part CMP-0073732-2, "Dual, 1-A, Low Noise (3.8-uVRMS), LDO Voltage Regulator, RTJ0020D (WQFN-20)"
U6: library part CMP-0029856-2, "Tiva C Series Microcontroller, 1024 KB Flash, 256 KB SRAM, 12 Bit, 20 Channels, -40 to 105 degC, 128-Pin TQFP (PDT), Green (RoHS & no Sb/Br), Tray"
U7: library part CMP-0033001-1, "Precision Micropower Shunt Voltage Reference, 0.5% accuracy, 2.5 V, 15 ppm / degC, 15 mA, -40 to 125 degC, 3-pin SOT-23 (DBZ), Green (RoHS & no Sb/Br)"
U8: library part CMP-0013883-2, "Four-Phase 2.5-A-per-Phase Buck Converter With Integrated Switches, RNF0026C (VQFN-HR-26)"
U9 U11: library part CMP-0036402-2, "Single Output High PSRR LDO, 1 A, Adjustable 1.2 to 5.5 V Output, 2.7 to 5.5 V Input, 8-pin SON (DRB), -40 to 125 degC, Green (RoHS & no Sb/Br)"
U10: library part CMP-0043115-1, "ESD-Protection Array for High-Speed Data Interfaces, 4 Channels, -40 to +85 degC, 6-pin SON (DRY), Green (RoHS & no Sb/Br)"
U12 U13: library part CMP-0067397-2, "1.4V-Capable +/-0.5degC Temperature Sensor with Alert Function and I2C/SMBus interface in SOT-563, DRL0006A (SOT-OTHER-6)"
U14: library part CMP-0067415-1, "10-Ohm Quad SPDT Analog Switch, RSV0016A (UQFN-16)"
Y1: library part CMP-0004694-3, "Crystal, 40 MHz, 8pF, SMD"
Y2: library part CMP-0078214-2, "Crystal, 16 MHz, 15 ppm, 8 pF, AEC-Q200 Grade 1, SMD"
ZZ1: library part AssemblyNoteLabel
ZZ2 ZZ3 ZZ4 ZZ5: library part AssemblyNote

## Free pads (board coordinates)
  round 275.59 / inner round 204.72 / far side round 275.59 hole 157.48: 1(2646.7,406.05) 2(2646.7,2306.05)
  round 160 hole 160 unplated mask+0: ""(102.75,162.5) ""(102.75,1570.6) ""(102.75,2402.5) ""(3136.31,162.5) ""(3136.31,2402.5)

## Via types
v1: diameter 22.4, hole 12.2, TOP to BOTTOM, tented both sides, 1046 vias
v2: diameter 15.74, hole 5.9, TOP to L2-GND1, tented both sides, 700 vias
v3: diameter 19.68, hole 7.87, TOP to BOTTOM, tented both sides, 9 vias

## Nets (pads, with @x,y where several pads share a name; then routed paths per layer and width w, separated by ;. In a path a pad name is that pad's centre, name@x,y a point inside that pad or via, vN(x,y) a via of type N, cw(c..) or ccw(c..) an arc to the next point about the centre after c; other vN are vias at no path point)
3V3_BRD: C41.2 C42.2 C43.2 C50.2 C61.2 C76.2 C77.2 C78.2 R3.2 R124.2 R127.2 R134.2 R140.2 R155.2 R156.2 R196.2 R197.2 R200.2 R201.2 U6.7 U6.8 U6.16 U6.26 U6.28 U6.39 U6.47 U6.51 U6.52 U6.69 U6.79 U6.90 U6.101 U6.113 U6.122 U9.3 U9.4 | length 6414.3
  TOP w15: v1(282.25,1045.5) 287.65,1050.9 R201.2@287.65,1073.71 301.46,1059.9 R200.2@325.45,1059.9 ; v1(1484.6,1080.35) 1484.6,1102.25 1532.35,1150 1611.55,1150 1628.76,1167.21 1629.15,1167.6 1629.15,1158.6 1712.65,1075.1 1712.65,1032.1 1755.65,989.1 1812.05,989.1 1890.65,1067.7 R196.2@1890.65,1125.31 R196.2@1890.65,1126.1
  TOP w20: R197.2@280.55,1160 R197.2@280.55,1159.21 280.55,1136.4 253.15,1109 253.15,1065.5 273.15,1045.5 v1(282.25,1045.5)
  L3-GND/SIG w15: v1(747.85,1061.4) 787.85,1101.4 866.37,1101.4 948.67,1183.7 1059.99,1183.7 1081.59,1162.1 1401.18,1162.1 1408.6,1154.68 1410.27,1154.68 v1(1484.6,1080.35)
  BOTTOM w7: 264.6,1560.15 311.39,1560.15 356.09,1560.15 ; 268.98,1402.67 U6.16@311.39,1402.67 358.32,1402.67 ; 274.11,1591.64 U6.28@311.39,1591.64 356.99,1591.64 ; U6.7@311.39,1260.93 360,1260.93 368.42,1269.35 361.09,1276.68 U6.8@311.39,1276.68 ; 464.93,1062.48 U6.122@464.93,1107.39 464.93,1153.92 ; 464.93,1674.68 U6.39@464.93,1713.69 464.93,1758.48 ; U6.47@590.92,1713.69 590.92,1745 602.43,1756.51 ; U6.113@606.67,1107.39 606.67,1137.06 623.61,1154 ; U6.51@653.91,1713.69 653.91,1767.91 660.86,1774.86 661.05,1775.05 661.24,1774.86 669.66,1766.44 U6.52@669.66,1713.69 ; 795.64,1066 U6.101@795.64,1107.39 795.64,1157.11 ; 869.75,1261 917.62,1261 U6.90@917.69,1260.93 ; 869.88,1591.64 U6.69@917.69,1591.64 953.12,1591.64 ; 873.05,1434.16 U6.79@917.69,1434.16
  BOTTOM w8: R155.2@795.64,1042.66 795.64,1043.34 795.64,1066 ; 953.12,1591.64 967.86,1576.9 995.5,1576.9
  BOTTOM w8.4: 462.75,1672.5 464.93,1674.68 ; R155.2@795.53,1042.55 R155.2@795.64,1042.66 ; 995.5,1576.9 996.09,1577.49
  BOTTOM w12: C50.2@248.96,1591.64 274.11,1591.64
  BOTTOM w15: C78.2@169.85,1002.35 170.04,1002.16 178.38,993.82 U9.3@178.38,953.94 ; U9.4@203.97,953.94 203.97,994.75 210.88,1001.66 C77.2@211.57,1002.35 ; C61.2@249.7,1402.56 249.81,1402.67 250.09,1402.67 268.98,1402.67
  BOTTOM w20: C78.2@169.85,1002.35 210.57,1002.35 211.57,1002.35 239.45,1002.35 282.25,1045.15 v1(282.25,1045.5) 322.05,1005.7 403.05,1005.7 441,1043.65 C76.2@464.67,1043.65 ; U9.4@203.97,953.94 227.43,953.94 260.39,920.98 R156.2@260.78,920.59 ; C50.2@248.96,1591.64 248.89,1591.71 248.7,1591.9 C50.2@248.7,1591.51 248.7,1576.05 264.6,1560.15 ; R140.2@249.3,1362.02 249.3,1402.16 C61.2@249.7,1402.56 ; 356.09,1560.15 386.6,1560.15 403.75,1543 ; 356.99,1591.64 396.89,1591.64 462.75,1657.5 462.75,1672.5 ; 358.32,1402.67 388.42,1402.67 403.75,1418 ; 368.42,1269.35 404.7,1269.35 461.55,1212.5 464.93,1212.5 ; 464.93,1062.48 464.67,1062.22 C76.2@464.67,1044.04 C76.2@464.67,1043.65 ; 464.93,1153.92 464.93,1212.5 ; 464.93,1758.48 C43.2@464.93,1772.66 ; C43.2@464.93,1772.71 465.08,1772.86 467.27,1775.05 583.89,1775.05 ; 623.61,1154 644.61,1175 777.75,1175 795.64,1157.11 816.75,1178.22 816.75,1237 840.75,1261 869.75,1261 ; R124.2@740.47,1775.45 700.87,1775.45 661.45,1775.45 661.05,1775.05 C42.2@620.97,1775.05 ; v1(747.85,1061.4) 751.36,1061.4 770.21,1042.55 ; 795.64,1066 795.53,1065.89 R155.2@795.53,1043.34 795.53,1042.55 770.21,1042.55 ; 869.88,1591.64 808.61,1591.64 792.75,1607.5 468.25,1607.5 403.75,1543 ; 873.05,1434.16 805.71,1434.16 743.55,1372 501.75,1372 475.75,1346 ; 996.09,1577.49 1004.74,1577.49 1016.3,1589.05 R134.2@1016.3,1603.1 ; 403.75,1418 403.75,1543 ; 403.75,1418 475.75,1346 ; C76.2@464.67,1043.65 490.1,1043.65 507.75,1026 507.75,1005.5 544.75,968.5 663.55,968.5 705.15,1010.1 737.76,1010.1 770.21,1042.55 ; 464.93,1212.5 487.75,1235.32 487.75,1334 475.75,1346 ; 583.89,1775.05 602.43,1756.51 620.78,1774.86 C42.2@620.97,1775.05 ; 583.89,1775.05 C42.2@620.97,1775.05
3V3_MON_XDS_1: R158.2 R159.2 U9.8 | length 106
  BOTTOM w15: R159.2@127.18,771.11 R159.2@127.18,771.9 U9.8@127.18,835.81
  BOTTOM w20: R159.2@127.18,771.11 168.29,771.11 R158.2@168.43,771.25
5V_IN: C86.2 FB1.2 FB2.2 P5.1 R34.2 R78.2 R100.2 R103.2 R115.2 R117.2 R118.1 R149.2 R176.2 R194.1 U11.1 U11.2 | length 1919.9
  TOP w20: R103.2@91.42,662.57 v1(91.42,694) ; v1(316.75,652) 318.75,652 318.75,652.66 R100.2@345.66,652.66 ; R117.2@411.36,573.55 411.75,573.94 419.75,581.94 v1(419.75,614) ; v1(634.6,1319.29) 647.65,1306.24 R194.1@647.65,1273.97 ; v1(942.75,1042.5) R78.2@1053.06,1042.5 R78.2@1053.85,1042.5 ; FB1.2@1588.03,646.07 1589.5,644.6 1598.05,644.6 1712.25,644.6 1819.15,751.5 1819.15,962.7 1943.45,1087 1993.75,1087 v1(2018.75,1112)
  TOP w30: v1(91.42,694) 70.75,694 46.75,718 46.75,822.5 R176.2@98.75,874.5
  BOTTOM w20: v1(91.42,694) 114.41,671.05 147.77,671.09 162.44,671.09 188.85,697.5 188.85,705.7 208.85,725.7 243.05,725.7 v1(316.75,652) ; v1(2018.75,1112) 2018.89,1112.14 R149.2@2018.89,1144.96 R149.2@2018.89,1145.75
  BOTTOM w30: v1(316.75,652) 381.75,652 v1(419.75,614) 419.75,577 v1(553.75,443)
  other v1: 664.75,382 612.75,384 576.75,404 455.65,1258 455.65,1290 1702.05,2302.5 1663.75,2304 1622.75,2319 1688.45,2341.4 1646.75,2347
5V_UNREG: C59.2 C60.2 C68.2 C72.2 C73.2 P5.2 R118.2 U8.9 U8.13 U8.18 U8.22 U8.26 | length 337.1
  TOP w25: v1(1832.75,594) 1818.75,594 1788.76,564.01 R118.2@1788.76,542.25 ; v1(1841.75,559) 1825,542.25 R118.2@1788.76,542.25 ; v1(1846.75,520) 1845.75,519 1812.01,519 R118.2@1788.76,542.25
  BOTTOM w10: U8.18@1728.55,1233.16 1770.41,1233.16 1773.95,1236.7 1807.25,1236.7 1820.45,1223.5 C68.2@1822.51,1223.5 1822.9,1223.5 1822.9,1253 v1(1822.75,1253)
  other v1: 1801.3,1020.3 1801.3,1052.3 1527.95,1076.8 1798.75,1083 1558.05,1084.6 1766.75,1091 1736.75,1101 1578.55,1107.4 1533.75,1114 1569.75,1370.5 1745.3,1370.3 1776.3,1370.3 1540.75,1373.5
+3.3VD: C5.2 C20.2 C84.2 C87.2 C97.2 P2.2 P3.2 P4.2 R14.2 R15.2 R16.2 R37.1 R38.2 R41.2 R43.2 R68.2 R74.2 R90.2 R91.2 R130.2 R133.2 R170.2 R171.2 R172.2 R173.2 R177.1 R206.2 U2.F15 U2.R10 U3.5 U14.14 | length 10789.5
  TOP w8: 1083.34,1356.75 1104.73,1356.75 1118.21,1343.27 1118.21,1338.17 1126.3,1330.08 U14.14@1139.03,1330.08
  TOP w10: v1(2096.75,1584.5) 2105.75,1584.5 2110.47,1589.22 U2.F15@2218.17,1589.22 ; v1(2343.95,1881) 2346.12,1878.83 U2.R10@2346.12,1819.53
  TOP w15: v1(1090.95,991.5) 1107.85,1008.4 1271.45,1008.4 1314.8,1051.75 R177.1@1349.25,1051.75
  TOP w20: R74.2@135.5,1383.64 v1(135.5,1422) ; R91.2@245.27,918.87 R91.2@245.27,919.66 245.27,963.02 v1(251.75,969.5) ; R90.2@303.21,919.19 332.96,919.19 v1(354.7,897.45) ; v1(318.75,1734.55) R68.2@348.79,1734.55 ; v1(777.72,1211.5) 777.72,1215.88 898.92,1337.08 R206.2@898.92,1379.34 881.01,1361.43 v1(848.67,1361.43) ; v1(995.9,1390.05) 997.29,1390.05 1009.36,1377.99 1009.36,1376.59 1021.92,1364.03 C97.2@1021.92,1361.93 1027.1,1356.75 1083.34,1356.75 ; v1(1090.95,991.5) 1089.24,989.79 1089.24,961.35 1089.44,961.15 U3.5@1144.06,961.15 ; R15.2@1216.75,2281.45 R15.2@1216.75,2280.66 1216.75,2234.3 v1(1223.15,2227.9) ; v1(1741.8,2033.85) 1762.45,2054.5 R43.2@1766.26,2054.5 R43.2@1767.05,2054.5 ; v1(1741.81,2190) 1765.99,2190 R38.2@1771.65,2184.34 ; C84.2@2037.05,1584.5 C84.2@2037.44,1584.5 v1(2096.75,1584.5) ; R41.2@2240.2,2113.48 2240.2,2109.6 2260.2,2089.6 2260.95,2089.6 v1(2260.95,2088.1) ; R37.1@2252.25,2208.8 2266.15,2208.8 2283.25,2191.7 2283.25,2147.1 v1(2268.55,2132.4) ; C5.2@2314.7,1910.8 2316.6,1908.9 2344.55,1908.9 2358.05,1922.4 C87.2@2364.55,1922.4
  L3-GND/SIG w20: v1(848.67,1361.43) 967.28,1361.43 v1(995.9,1390.05) ; v1(862.63,370.88) 863.69,369.82 v1(972.93,369.82) 980.11,377 1373.55,377 1407.75,342.8 v1@1407.75,273 ; v1(1483.75,1807) 1483.75,1828.8 1642.95,1988 1717.35,1988 1741.8,2012.45 v1(1741.8,2033.85) ; v1(1741.81,2190) 1754.21,2177.6 2068.35,2177.6 2113.55,2132.4 v1(2268.55,2132.4)
  L3-GND/SIG w30: P4.2@921.19,931.25 1030.7,931.25 1087.75,874.2 1087.75,806.4 1133.65,760.5 v1(1155.75,760.5)
  L3-GND/SIG w35: v1(135.5,1422) 176.1,1381.4 241.45,1381.4 308.15,1314.7 308.15,1193.4 344.45,1157.1 344.45,1044 269.95,969.5 v1(251.75,969.5) 251.75,932.01 286.03,897.73 354.42,897.73 v1(354.7,897.45) 389.17,931.92 411.67,931.92 ; P4.2@921.19,931.25 921.19,960.94 995.65,1035.4 1059.75,1035.4 1090.95,1004.2 v1(1090.95,991.5)
  L3-GND/SIG w40: 411.67,931.92 P3.2@511.75,931.92 512.08,932.25 P2.2@715.19,932.25 717.44,930 919.94,930 P4.2@921.19,931.25
  L4-GND/SIG w20: v1(135.5,1422) 318.75,1605.25 v1(318.75,1734.55) ; v1(702.75,2012) 656.55,1965.8 589.35,1965.8 543.25,2011.9 510.75,2011.9 482.75,2039.9 v1(482.75,2051.5) 461.75,2072.5 461.75,2341.5 613.85,2493.6 709.65,2493.6 748.35,2454.9 909.45,2454.9 961.35,2403 975.55,2403 ; v1(1223.15,2227.9) 1217.25,2233.8 1217.25,2273 1190.45,2299.8 1078.75,2299.8 1060.35,2318.2 1060.35,2318.3 1060.25,2318.3 975.55,2403 ; v1(1741.8,2033.85) 1741.8,2034.95 1751.45,2044.6 1751.45,2180.36 v1(1741.81,2190) 1753.05,2201.24 1753.05,2410.2 1694.75,2468.5 1459.25,2468.5 1426.15,2501.6 v1(1087.35,2501.6) 1087.35,2475.1 1059.95,2447.7 1018.75,2447.7 975.55,2404.5 975.55,2403 ; v1(2096.75,1584.5) 2105.75,1593.5 2189.25,1593.5 2238.15,1642.4 2238.15,1775.2 v1(2343.95,1881) 2343.95,2005.1 v1(2260.95,2088.1) 2260.95,2124.8 v1(2268.55,2132.4)
  L4-GND/SIG w40: v1(777.72,1211.5) 777.72,1174.02 905.55,1046.19 905.55,1027.09 921.19,1011.45 P4.2@921.19,931.25
  BOTTOM w20: v1(318.75,1734.55) 318.75,1832.5 388.25,1902 388.25,1957 v1(482.75,2051.5) ; v1(702.75,2012) 706.25,2008.5 R16.2@732.06,2008.5 R16.2@732.85,2008.5 ; R173.2@862.63,342.55 R173.2@862.63,343.34 v1(862.63,370.88) ; v1(972.93,369.82) R172.2@972.93,343.34 972.93,342.55 1018.11,342.55 1086.05,410.49 1086.05,732 1114.55,760.5 v1(1155.75,760.5) ; v1(1087.35,2501.6) 1090.85,2505.1 R14.2@1125.96,2505.1 R14.2@1126.75,2505.1 ; v1@1407.75,273 1428.45,273 1435.55,280.1 ; R171.2@1418.12,307.45 R171.2@1418.12,306.66 1418.12,300.63 1435.55,283.2 1435.55,280.1 ; R170.2@1530.77,307.45 1503.42,280.1 1435.55,280.1
  BOTTOM w25: R130.2@1471.56,1761.21 1471.56,1794.81 v1(1483.75,1807)
  other v1: 1410.75,269.5
AR_1P3_RF1: C36.2 C37.2 C38.2 C45.2 C46.2 C47.2 R131.2 R195.2 U2.G5 U2.H5 U2.J5 U5.14 U5.15 | length 94.3
  TOP w10: U2.G5@2474.07,1614.81 U2.H5@2474.07,1640.4 U2.J5@2474.07,1665.99
  TOP w15: U2.G5@2474.07,1614.81 2487.06,1614.81 v1(2491.75,1619.5) ; U2.J5@2474.07,1665.99 v1(2497.58,1665.99)
  other v1: 1840.75,1798.5 1865.85,1822.1
AR_1P3_RF2: C28.2 C33.2 C34.2 C35.2 C57.2 C58.2 L6.2 R122.2 R137.1 R195.1 U2.C2 U2.D2 U5.11 U5.12 | length 162.3
  TOP w20: U2.C2@2550.84,1512.45 U2.D2@2550.84,1538.04 2583.51,1538.04 2623.1,1498.45 v1(2623.1,1480.6)
  TOP w25: v1(2623.1,1480.6) 2651.85,1480.6 v1(2652.85,1479.6)
  other v1: 1835.45,1973.3 1866.25,1973.2
AR_1V4_APLL: C13.2 U2.A10 | length 86.4
  TOP w12: 2341.05,1452.5 2341.05,1456.2 U2.A10@2346.12,1461.27
  TOP w20: C13.2@2329.25,1381.9 2341.05,1393.7 2341.05,1452.5
AR_1V4_SYNTH: C14.2 U2.A13 | length 121.2
  TOP w12: 2262.85,1443.1 2269.35,1449.6 U2.A13@2269.35,1461.27
  TOP w15: C14.2@2187.2,1383.4 2197.7,1393.9 2213.65,1393.9 2262.85,1443.1
AR_1V8: C12.2 C17.2 C18.2 C19.2 C39.2 C48.2 C51.2 C52.2 C53.2 C90.2 L5.2 R82.2 U2.B11 U2.B12 U2.E15 U2.F5 U2.K5 U2.R9 U4.1 U4.2 | length 1034.9
  TOP w10: v1(2168.75,1544.5) 2187.88,1563.63 U2.E15@2218.17,1563.63 ; U2.R9@2371.71,1819.53 2371.71,1856.16 v1(2381.75,1866.2)
  TOP w12: 2294.94,1431.89 U2.B12@2294.94,1486.86
  TOP w14: C90.2@2257.75,1291.8 2257.94,1291.99 2262.17,1296.22 2273.87,1296.22 2296.75,1319.1 2296.75,1404.89 2316.55,1424.69 ; C12.2@2269.95,1391 C12.2@2269.95,1391.39 2269.95,1406.9 2294.94,1431.89 ; 2316.55,1476.6 2316.55,1482.88 U2.B11@2320.53,1486.86
  TOP w15: U2.F5@2474.07,1589.22 2478.03,1589.22 2484.75,1582.5 2486.74,1582.5 2489.21,1580.03 v1(2490.75,1580.03) ; U2.K5@2474.07,1691.58 2476.73,1691.58 v1(2494.52,1709.37)
  TOP w20: v1(2235.15,1359.9) 2236.55,1361.3 2236.55,1368.7 2258.85,1391 C12.2@2269.95,1391 ; 2316.55,1424.69 2316.55,1476.6
  L3-GND/SIG w8: 2463.35,1784.3 2463.35,1734.9 2470.75,1727.5
  L3-GND/SIG w20: v1(2381.75,1866.2) 2381.75,1865.9 2463.35,1784.3 ; 2470.75,1727.5 2488.88,1709.37 v1(2494.52,1709.37)
  BOTTOM w10: v1(2207.75,1172) 2236.58,1143.17 L5.2@2242.55,1143.17
  BOTTOM w20: v1(2168.75,1544.5) 2169.05,1544.8 2202.65,1544.8 2215.4,1557.55 C53.2@2215.4,1576.5 ; C48.2@2381.75,1830.2 C48.2@2381.75,1830.59 v1(2381.75,1866.2) ; v1(2490.75,1580.03) 2493.23,1580.03 2517.9,1604.7 C51.2@2539.9,1604.7 ; v1(2494.52,1709.37) 2494.52,1711.47 2540.85,1757.8 C39.2@2545.11,1757.8 C39.2@2545.5,1757.8
  other v1: 2190.75,1133 2197.75,1207 2194.95,1239.1
AR_ANAMUX: P1.3 U2.B13 | length 2912.2
  TOP w4: v1(2201.35,1419.4) 2219.75,1419.4 2256.35,1456 2256.35,1466.2 2269.35,1479.2 U2.B13@2269.35,1486.86
  L3-GND/SIG w5: P1.3@109.02,1808.65 167.75,1749.92 167.75,1657.7 280.15,1545.3 280.15,1518.95 387.6,1411.5 435.75,1411.5 713.95,1133.3 861.91,1133.3 937.31,1208.7 1070.55,1208.7 1088.95,1190.3 1354.35,1190.3 1369.52,1205.47 1439.67,1205.47 1497.45,1263.25 1497.45,1490.28 1544.29,1537.12 1959.13,1537.12 2076.85,1419.4 v1(2201.35,1419.4)
AR_ANATEST1: R104.2 U2.P1 | length 3580.4
  TOP w4: R104.2@830.5,674.77 831.27,674 v1(866.75,674) ; U2.P1@2576.43,1793.94 2583.17,1793.94 2672.45,1883.22 v1(2672.45,1902.1)
  L3-GND/SIG w5: v1(866.75,674) 905.44,674 1041.94,537.5 1729.05,537.5 1845.6,654.05 1910.13,654.05 1979.75,584.43 1979.75,452.5 2011.75,420.5 2147.55,420.5 2147.65,420.4 2155.85,420.4 2155.95,420.5 2176.95,420.5 2812.45,1056 2812.45,1762.1 v1(2672.45,1902.1)
AR_ANATEST2: R94.2 U2.P2 | length 3500.9
  TOP w4: R94.2@931,707.77 939.23,716 v1(966.75,716) ; U2.P2@2550.84,1793.94 2563.7,1806.8 2563.7,1824.85 2617.65,1878.8 v1(2635.85,1878.8)
  L3-GND/SIG w5: v1(966.75,716) 991.8,690.95 991.8,609.76 1051.11,550.45 1725.2,550.45 1838.8,664.05 1914.28,664.05 1990.75,587.58 1990.75,467.51 2027.76,430.5 2168.25,430.5 2795.25,1057.5 2795.25,1762.4 2692.15,1865.5 2649.15,1865.5 v1(2635.85,1878.8)
AR_ANATEST3: R105.2 U2.P3 | length 3561.2
  TOP w4: R105.2@1032.5,674.77 1043.47,674.77 1056.55,661.69 v1(1056.55,594.9) ; U2.P3@2525.25,1793.94 2538.2,1806.89 2538.2,1829.45 2632.75,1924 v1(2632.75,1997.5)
  L3-GND/SIG w5: v1(1056.55,594.9) 1090.95,560.5 1719.15,560.5 1832.7,674.05 1918.43,674.05 2001.75,590.73 2001.75,475.5 2032.75,444.5 2160.55,444.5 2780.25,1064.2 2780.25,1636.2 2619.75,1796.7 2619.75,1858.5 2610.75,1867.5 2610.75,1975.5 v1(2632.75,1997.5)
AR_ANATEST4: R106.2 U2.R2 | length 3518.6
  TOP w4: R106.2@1133,674.77 1142.88,674.77 1169.45,648.2 v1(1169.45,635.9) ; U2.R2@2550.84,1819.53 2550.84,1830.09 2675.25,1954.5 v1(2675.25,2005)
  L3-GND/SIG w5: v1(1169.45,635.9) 1186.05,652.5 1353.77,652.5 1430.77,575.5 1719.95,575.5 1828.5,684.05 1922.58,684.05 2013.75,592.88 2013.75,478.5 2037.75,454.5 2146.25,454.5 2762.25,1070.5 2762.25,1622.2 2567.75,1816.7 2567.75,1864.5 2598.75,1895.5 2598.75,2013.5 2612.75,2027.5 2652.75,2027.5 v1(2675.25,2005)
AR_BSS_LOGGER: R31.1 R135.1 U2.H14 | length 4498.7
  TOP w4: v1(1272.25,1494.3) 1283.15,1505.2 1302.01,1505.2 1308.66,1498.55 1308.66,1491.95 1315.5,1485.11 1323.08,1485.11 1328.62,1490.65 1328.62,1498.96 1334.86,1505.2 1346.45,1505.2 1420.95,1579.7 1934.2,1579.7 2007.69,1653.19 2230.97,1653.19 U2.H14@2243.76,1640.4 ; R31.1@1279.5,2305.21 1279.5,2320.09 1294.87,2335.46 1302.76,2335.46 1304.75,2333.47 v1(1304.75,2315.5)
  L4-GND/SIG w5: v1(541.75,2182.5) 570.15,2210.9 894.75,2210.9 965.05,2281.2 1122.81,2281.2 1206.51,2197.5 1270.75,2197.5 1289.75,2216.5 1289.75,2246.5 1282.05,2254.2 1282.05,2292.8 v1(1304.75,2315.5)
  BOTTOM w4: R135.1@224.54,1528.69 224.54,1782.19 351.25,1908.9 351.25,1961.1 476.65,2086.5 490.45,2086.5 541.75,2137.8 v1(541.75,2182.5) ; v1(1272.25,1494.3) 1272.25,1460 1279.75,1452.5 1279.75,1413.4 1274.55,1408.2 1268.05,1408.2 1261.75,1414.5 1261.75,1439.49 1254.74,1446.5 1229.75,1446.5 1222.58,1453.67 1222.58,1460.23 1228.35,1466 1238.25,1466 1247.95,1475.7 1247.95,1498.3 1235.75,1510.5 1235.75,1518.5 1240.75,1523.5 1277.75,1523.5 1281.75,1527.5 1281.75,1534.5 1274.75,1541.5 1239.75,1541.5 1235.75,1545.5 1235.75,1579.3 1279.75,1623.3 1279.75,1640.41 1275.06,1645.1 1265.34,1645.1 1260.65,1649.79 1260.65,1656.41 1265.34,1661.1 1275.06,1661.1 1279.75,1665.79 1279.75,1672.41 1275.06,1677.1 1265.34,1677.1 1260.65,1681.79 1260.65,1688.41 1265.34,1693.1 1275.06,1693.1 1279.75,1697.79 1279.75,1704.41 1275.06,1709.1 1265.34,1709.1 1260.65,1713.79 1260.65,1720.41 1265.34,1725.1 1275.06,1725.1 1279.75,1729.79 1279.75,1736.41 1275.06,1741.1 1265.34,1741.1 1260.65,1745.79 1260.65,1752.41 1265.34,1757.1 1275.06,1757.1 1279.75,1761.79 1279.75,1770.79 1275.06,1775.48 1240.37,1775.48 1235.48,1780.37 1235.48,1786.99 1239.97,1791.48 1275.06,1791.48 1279.75,1796.17 1279.75,1815.5 1272.4,1822.85 1265.36,1822.85 1253.2,1810.69 1246.56,1810.69 1241.88,1815.37 1241.88,1822.01 1254.04,1834.17 1254.04,1840.81 1215.75,1879.1 1215.75,2030.5 1247.75,2062.5 1274.75,2062.5 1283.75,2071.5 1283.75,2098.5 1294.75,2109.5 1294.75,2201.5 1319.75,2226.5 1356.75,2226.5 1360.75,2230.5 1360.75,2243.5 1356.75,2247.5 1339.75,2247.5 1335.75,2251.5 1335.75,2262.5 1339.75,2266.5 1377.75,2266.5 1381.75,2270.5 1381.75,2279.8 1376.75,2284.8 1335.45,2284.8 v1(1304.75,2315.5)
AR_CS1: U2.C13 U14.10 | length 1413.6
  TOP w4: U14.10@1194.14,1353.71 1194.14,1368.1 1202.87,1376.83 1218.42,1376.83 1230.41,1388.82 1296.29,1388.82 1301.44,1383.67 1301.44,1373.51 1305.26,1369.69 1316.69,1369.69 1321.47,1374.47 1321.47,1385.39 1324.9,1388.82 1419.37,1388.82 1424.81,1383.38 1424.81,1377.04 1404.01,1356.24 1404.01,1337.67 1414.91,1326.77 1430.83,1326.77 1451.37,1347.31 1460.88,1347.31 1490.69,1317.5 1706.15,1317.5 1712.65,1311 1872.25,1311 1914.15,1269.1 2084.35,1269.1 2144.35,1329.1 2144.35,1406.5 2182.45,1444.6 2221.05,1444.6 2231.15,1454.7 2231.15,1468.1 2237.35,1474.3 2248.95,1474.3 2256.35,1481.7 2256.35,1499.45 U2.C13@2269.35,1512.45
AR_DMM_CLK: R54.1 U2.N15 | length 3079.5
  TOP w4: v1(956.25,1680.3) 924.05,1648.1 924.05,1627.1 936.65,1614.5 1205.95,1614.5 1290.05,1698.6 1351.45,1698.6 1376.75,1723.9 1376.75,1980.5 1391.75,1995.5 1438.75,1995.5 1444.75,1989.5 1444.75,1975.49 1440.06,1970.8 1398.44,1970.8 1393.75,1966.11 1393.75,1959.49 1398.44,1954.8 1440.06,1954.8 1444.75,1950.11 1444.75,1943.49 1440.06,1938.8 1398.44,1938.8 1393.75,1934.11 1393.75,1927.49 1398.44,1922.8 1440.06,1922.8 1444.75,1918.11 1444.75,1911.49 1440.06,1906.8 1398.44,1906.8 1393.75,1902.11 1393.75,1895.49 1398.44,1890.8 1440.06,1890.8 1444.75,1886.11 1444.75,1879.49 1440.06,1874.8 1398.44,1874.8 1393.75,1870.11 1393.75,1863.49 1398.44,1858.8 1440.06,1858.8 1444.75,1854.11 1444.75,1847.49 1440.06,1842.8 1398.44,1842.8 1393.75,1838.11 1393.75,1831.49 1398.44,1826.8 1440.06,1826.8 1444.75,1822.11 1444.75,1815.49 1440.06,1810.8 1398.44,1810.8 1393.75,1806.11 1393.75,1799.49 1398.44,1794.8 1440.06,1794.8 1444.75,1790.11 1444.75,1783.49 1440.06,1778.8 1398.44,1778.8 1393.75,1774.11 1393.75,1767.49 1398.44,1762.8 1467.66,1762.8 1478.86,1751.6 1872.25,1751.6 1931.25,1810.6 2122.25,1810.6 2164.5,1768.35 U2.N15@2218.17,1768.35
  L3-GND/SIG w5: v1(956.25,1680.3) 998.25,1722.3 998.25,1756.3 987.05,1767.5 965.85,1767.5 949.75,1783.6 949.75,1823.4 964.65,1838.3 964.65,1884.9 964.75,1885 964.75,1885.5 996.45,1917.2 1043.59,1917.2 1101.77,1975.51 v1(1101.75,2001.5)
  BOTTOM w4: R54.1@1086.75,2023.51 1101.75,2008.51 v1(1101.75,2001.5)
